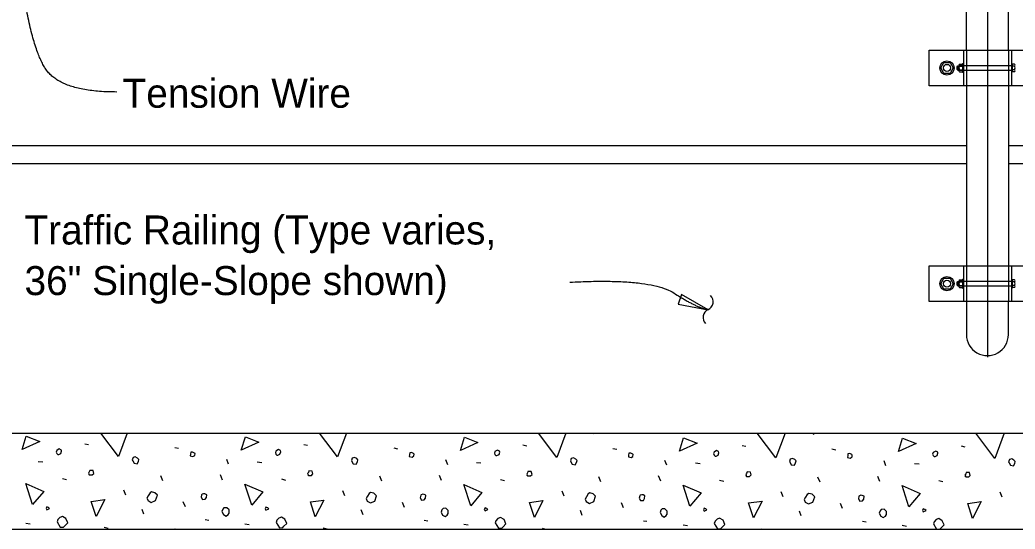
# Model space of a CAD drawing. Extents: x 0.5 to 39.7, y 0.9 to 25.6.
# Drawn here: x 5.48 to 12.4, y 13.47 to 17.01 of the extents above; entities that cross this region are included whole.
import ezdxf

# ---------------------------------------------------------------- set-up
doc = ezdxf.new("R2010")
doc.units = 0
for name, color, linetype in [('CL_Major', 7, 'Continuous'), ('Dimension', 7, 'Continuous'), ('Miscellaneous', 7, 'Continuous'), ('SteelMisc', 7, 'Continuous'), ('SteelMisc_h', 7, 'Continuous'), ('SupstrConc', 7, 'Continuous'), ('TextStructures', 7, 'Continuous')]:
    doc.layers.add(name, color=color, linetype=linetype)

msp = doc.modelspace()

# ---------------------------------------------------------------- linework, layer by layer
at = {"layer": 'CL_Major'}
msp.add_line((12.2062, 24.6326), (12.2062, 14.6639), dxfattribs=at)
at = {"layer": 'Dimension'}
msp.add_lwpolyline([(10.2634, 14.9952), (10.0798, 15.0997), (10.0556, 15.0334)], close=True, dxfattribs=at)
for centre, start, end in [((10.2392, 15.0503), 294.14658, 45.87379), ((10.2879, 14.9415), 114.14657, 225.87379)]:
    msp.add_arc(centre, 0.0596, start, end, dxfattribs=at)
for points in [[(6.1508, 16.5088), (5.753, 16.5088), (5.549, 16.8458), (5.4877, 17.3027)], [(9.3027, 15.1869), (9.8656, 15.2152), (10.187, 15.0071), (10.2636, 14.9959)]]:
    msp.add_open_spline(points, degree=2, dxfattribs=at)
at = {"layer": 'Miscellaneous'}
for p, q in [((11.9986, 16.6691), (11.9986, 16.6812)), ((12.0044, 16.6691), (12.0044, 16.6812)), ((11.9986, 15.1691), (11.9986, 15.1812)), ((12.0044, 15.1691), (12.0044, 15.1812)), ((7.9504, 14.1326), (7.9491, 14.1361)), ((9.4742, 14.129), (9.4716, 14.1361)), ((10.9981, 14.1255), (10.9942, 14.1361)), ((5.9281, 14.0619), (5.9546, 14.0566)), ((7.4519, 14.0583), (7.4784, 14.053)), ((8.9757, 14.0548), (9.0023, 14.0495)), ((10.4996, 14.0513), (10.5261, 14.046)), ((6.5539, 14.0371), (6.5804, 14.0318)), ((8.0777, 14.0336), (8.1042, 14.0283)), ((9.6015, 14.0301), (9.628, 14.0247)), ((11.1253, 14.0265), (11.1519, 14.0212)), ((12.0234, 14.0477), (12.0499, 14.0424)), ((5.6046, 13.9399), (5.6364, 13.9364)), ((6.9287, 13.9205), (6.9163, 13.954)), ((7.1284, 13.9364), (7.1602, 13.9328)), ((8.4525, 13.9169), (8.4401, 13.9505)), ((8.6522, 13.9328), (8.6841, 13.9293)), ((9.9763, 13.9134), (9.9639, 13.947)), ((10.1761, 13.9293), (10.2079, 13.9258)), ((11.5001, 13.9098), (11.4877, 13.9434)), ((11.6999, 13.9258), (11.7317, 13.9222)), ((6.8862, 13.8108), (6.8721, 13.8462)), ((5.7725, 13.8215), (5.8008, 13.8144)), ((6.4708, 13.8055), (6.4567, 13.8409)), ((7.2964, 13.8179), (7.3246, 13.8108)), ((7.9946, 13.802), (7.9805, 13.8374)), ((8.4101, 13.8073), (8.3959, 13.8427)), ((8.8202, 13.8144), (8.8485, 13.8073)), ((9.5184, 13.7985), (9.5043, 13.8338)), ((9.9339, 13.8038), (9.9197, 13.8391)), ((10.344, 13.8108), (10.3723, 13.8038)), ((11.0423, 13.7949), (11.0281, 13.8303)), ((11.4577, 13.8002), (11.4435, 13.8356)), ((11.8678, 13.8073), (11.8961, 13.8002)), ((6.2145, 13.7048), (6.2003, 13.7401)), ((7.7383, 13.7012), (7.7242, 13.7366)), ((9.2621, 13.6977), (9.248, 13.7331)), ((10.7859, 13.6942), (10.7718, 13.7295)), ((12.3097, 13.6906), (12.2956, 13.726)), ((6.6281, 13.6235), (6.614, 13.6588)), ((8.152, 13.6199), (8.1378, 13.6553)), ((9.6758, 13.6164), (9.6616, 13.6518)), ((11.1996, 13.6129), (11.1854, 13.6482)), ((6.34, 13.5722), (6.3276, 13.6058)), ((7.8638, 13.5687), (7.8514, 13.6023)), ((9.3876, 13.5651), (9.3753, 13.5987)), ((10.9114, 13.5616), (10.8991, 13.5952)), ((5.518, 13.5103), (5.548, 13.505)), ((6.766, 13.5351), (6.7908, 13.5315)), ((7.0418, 13.5068), (7.0719, 13.5015)), ((8.2898, 13.5315), (8.3146, 13.528)), ((8.5656, 13.5033), (8.5957, 13.498)), ((9.8137, 13.528), (9.8384, 13.5245)), ((10.0894, 13.4997), (10.1195, 13.4944)), ((11.3375, 13.5245), (11.3622, 13.5209)), ((6.0625, 13.482), (6.0907, 13.475)), ((7.5863, 13.4785), (7.6146, 13.4714)), ((9.1101, 13.475), (9.1322, 13.4695)), ((10.6339, 13.4714), (10.6418, 13.4695)), ((11.6132, 13.4962), (11.6433, 13.4909))]:
    msp.add_line(p, q, dxfattribs=at)
for points in [[(6.1632, 13.9753), (6.041, 14.1361)], [(6.2233, 14.1361), (6.1632, 13.9753)], [(7.687, 13.9717), (7.5621, 14.1361)], [(7.7485, 14.1361), (7.687, 13.9717)], [(9.2109, 13.9682), (9.0832, 14.1361)], [(9.2736, 14.1361), (9.2109, 13.9682)], [(10.7347, 13.9646), (10.6043, 14.1361)], [(10.7988, 14.1361), (10.7347, 13.9646)], [(12.2585, 13.9611), (12.1255, 14.1361)], [(12.3239, 14.1361), (12.2585, 13.9611)], [(5.4932, 14.023), (5.5215, 14.1149), (5.6152, 14.0778), (5.4932, 14.023)], [(7.0171, 14.0194), (7.0453, 14.1114), (7.139, 14.0742), (7.0171, 14.0194)], [(8.5409, 14.0159), (8.5692, 14.1078), (8.6628, 14.0707), (8.5409, 14.0159)], [(10.0647, 14.0124), (10.093, 14.1043), (10.1867, 14.0672), (10.0647, 14.0124)], [(11.5885, 14.0088), (11.6168, 14.1008), (11.7105, 14.0636), (11.5885, 14.0088)], [(5.7407, 13.9876), (5.7478, 13.9876), (5.7619, 13.9947), (5.7672, 14.0106), (5.7655, 14.0194), (5.7513, 14.0265), (5.7337, 14.0159), (5.7301, 14.0053), (5.7337, 13.9947), (5.7407, 13.9876)], [(6.6617, 13.9788), (6.6812, 13.9735), (6.6935, 13.9823), (6.6953, 13.9947), (6.6918, 13.9982), (6.6776, 14.0053), (6.6653, 14.0035), (6.6635, 13.9912), (6.6617, 13.9788)], [(7.2645, 13.9841), (7.2716, 13.9841), (7.2858, 13.9912), (7.2911, 14.0071), (7.2893, 14.0159), (7.2751, 14.023), (7.2575, 14.0124), (7.2539, 14.0018), (7.2575, 13.9912), (7.2645, 13.9841)], [(8.1855, 13.9753), (8.205, 13.9699), (8.2174, 13.9788), (8.2191, 13.9912), (8.2156, 13.9947), (8.2015, 14.0018), (8.1891, 14), (8.1873, 13.9876), (8.1855, 13.9753)], [(8.7884, 13.9806), (8.7954, 13.9806), (8.8096, 13.9876), (8.8149, 14.0035), (8.8131, 14.0124), (8.799, 14.0194), (8.7813, 14.0088), (8.7777, 13.9982), (8.7813, 13.9876), (8.7884, 13.9806)], [(9.7094, 13.9717), (9.7288, 13.9664), (9.7412, 13.9753), (9.7429, 13.9876), (9.7394, 13.9912), (9.7253, 13.9982), (9.7129, 13.9965), (9.7111, 13.9841), (9.7094, 13.9717)], [(10.3122, 13.977), (10.3192, 13.977), (10.3334, 13.9841), (10.3387, 14), (10.3369, 14.0088), (10.3228, 14.0159), (10.3051, 14.0053), (10.3016, 13.9947), (10.3051, 13.9841), (10.3122, 13.977)], [(11.2332, 13.9682), (11.2526, 13.9629), (11.265, 13.9717), (11.2668, 13.9841), (11.2632, 13.9876), (11.2491, 13.9947), (11.2367, 13.9929), (11.2349, 13.9806), (11.2332, 13.9682)], [(11.836, 13.9735), (11.8431, 13.9735), (11.8572, 13.9806), (11.8625, 13.9965), (11.8607, 14.0053), (11.8466, 14.0124), (11.8289, 14.0018), (11.8254, 13.9912), (11.8289, 13.9806), (11.836, 13.9735)], [(6.2622, 13.9434), (6.2711, 13.9275), (6.2923, 13.924), (6.3011, 13.9399), (6.3046, 13.954), (6.2958, 13.9629), (6.2799, 13.9717), (6.264, 13.9664), (6.2587, 13.9505), (6.2622, 13.9434)], [(7.786, 13.9399), (7.7949, 13.924), (7.8161, 13.9205), (7.8249, 13.9364), (7.8285, 13.9505), (7.8196, 13.9593), (7.8037, 13.9682), (7.7878, 13.9629), (7.7825, 13.947), (7.786, 13.9399)], [(9.3098, 13.9364), (9.3187, 13.9205), (9.3399, 13.9169), (9.3487, 13.9328), (9.3523, 13.947), (9.3434, 13.9558), (9.3275, 13.9646), (9.3116, 13.9593), (9.3063, 13.9434), (9.3098, 13.9364)], [(10.8337, 13.9328), (10.8425, 13.9169), (10.8637, 13.9134), (10.8726, 13.9293), (10.8761, 13.9434), (10.8672, 13.9523), (10.8513, 13.9611), (10.8354, 13.9558), (10.8301, 13.9399), (10.8337, 13.9328)], [(12.3575, 13.9293), (12.3663, 13.9134), (12.3875, 13.9098), (12.3964, 13.9258), (12.3999, 13.9399), (12.3911, 13.9487), (12.3752, 13.9576), (12.3592, 13.9523), (12.3539, 13.9364), (12.3575, 13.9293)], [(5.9599, 13.8462), (5.9811, 13.8462), (5.9917, 13.8568), (5.9864, 13.8763), (5.9635, 13.878), (5.9599, 13.8674), (5.9546, 13.8586), (5.9599, 13.8462), (5.9564, 13.8497)], [(7.4837, 13.8427), (7.505, 13.8427), (7.5156, 13.8533), (7.5103, 13.8727), (7.4873, 13.8745), (7.4837, 13.8639), (7.4784, 13.855), (7.4837, 13.8427), (7.4802, 13.8462)], [(9.0076, 13.8391), (9.0288, 13.8391), (9.0394, 13.8497), (9.0341, 13.8692), (9.0111, 13.871), (9.0076, 13.8603), (9.0023, 13.8515), (9.0076, 13.8391), (9.004, 13.8427)], [(10.5314, 13.8356), (10.5526, 13.8356), (10.5632, 13.8462), (10.5579, 13.8657), (10.5349, 13.8674), (10.5314, 13.8568), (10.5261, 13.848), (10.5314, 13.8356), (10.5278, 13.8391)], [(12.0552, 13.8321), (12.0764, 13.8321), (12.087, 13.8427), (12.0817, 13.8621), (12.0587, 13.8639), (12.0552, 13.8533), (12.0499, 13.8444), (12.0552, 13.8321), (12.0517, 13.8356)], [(5.5657, 13.6394), (5.518, 13.7861), (5.6435, 13.7313), (5.5657, 13.6394)], [(7.0895, 13.6358), (7.0418, 13.7826), (7.1673, 13.7278), (7.0895, 13.6358)], [(8.6133, 13.6323), (8.5656, 13.779), (8.6911, 13.7242), (8.6133, 13.6323)], [(10.1372, 13.6288), (10.0894, 13.7755), (10.2149, 13.7207), (10.1372, 13.6288)], [(6.3683, 13.6677), (6.3913, 13.6553), (6.4213, 13.6677), (6.4337, 13.7048), (6.416, 13.7225), (6.393, 13.7278), (6.3824, 13.7207), (6.37, 13.7012), (6.3612, 13.6853), (6.3683, 13.6677)], [(6.7377, 13.6906), (6.7466, 13.6747), (6.766, 13.6765), (6.7749, 13.6889), (6.7766, 13.7083), (6.7643, 13.7136), (6.7554, 13.7154), (6.7448, 13.7119), (6.7413, 13.7083), (6.7377, 13.6906)], [(7.8921, 13.6641), (7.9151, 13.6518), (7.9451, 13.6641), (7.9575, 13.7012), (7.9398, 13.7189), (7.9168, 13.7242), (7.9062, 13.7172), (7.8939, 13.6977), (7.885, 13.6818), (7.8921, 13.6641)], [(8.2616, 13.6871), (8.2704, 13.6712), (8.2898, 13.673), (8.2987, 13.6853), (8.3005, 13.7048), (8.2881, 13.7101), (8.2792, 13.7119), (8.2686, 13.7083), (8.2651, 13.7048), (8.2616, 13.6871)], [(9.4159, 13.6606), (9.4389, 13.6482), (9.4689, 13.6606), (9.4813, 13.6977), (9.4636, 13.7154), (9.4407, 13.7207), (9.4301, 13.7136), (9.4177, 13.6942), (9.4088, 13.6783), (9.4159, 13.6606)], [(9.7854, 13.6836), (9.7942, 13.6677), (9.8137, 13.6694), (9.8225, 13.6818), (9.8243, 13.7012), (9.8119, 13.7066), (9.8031, 13.7083), (9.7924, 13.7048), (9.7889, 13.7012), (9.7854, 13.6836)], [(10.9397, 13.6571), (10.9627, 13.6447), (10.9928, 13.6571), (11.0051, 13.6942), (10.9875, 13.7119), (10.9645, 13.7172), (10.9539, 13.7101), (10.9415, 13.6906), (10.9327, 13.6747), (10.9397, 13.6571)], [(11.3092, 13.68), (11.318, 13.6641), (11.3375, 13.6659), (11.3463, 13.6783), (11.3481, 13.6977), (11.3357, 13.703), (11.3269, 13.7048), (11.3163, 13.7012), (11.3127, 13.6977), (11.3092, 13.68)], [(11.661, 13.6252), (11.6132, 13.772), (11.7388, 13.7172), (11.661, 13.6252)], [(6.0077, 13.5581), (5.9741, 13.6624), (6.0678, 13.6747), (6.0077, 13.5581)], [(7.5315, 13.5545), (7.4979, 13.6588), (7.5916, 13.6712), (7.5315, 13.5545)], [(9.0553, 13.551), (9.0217, 13.6553), (9.1154, 13.6677), (9.0553, 13.551)], [(10.5791, 13.5475), (10.5455, 13.6518), (10.6392, 13.6641), (10.5791, 13.5475)], [(12.1029, 13.5439), (12.0693, 13.6482), (12.163, 13.6606), (12.1029, 13.5439)], [(5.6647, 13.604), (5.6842, 13.6129), (5.6771, 13.6199), (5.6647, 13.6252), (5.6594, 13.6129), (5.6647, 13.604)], [(6.8827, 13.5916), (6.8933, 13.5704), (6.911, 13.5598), (6.9251, 13.5704), (6.9322, 13.581), (6.9322, 13.6023), (6.9163, 13.6182), (6.8968, 13.6164), (6.888, 13.6076), (6.8827, 13.5916)], [(7.1885, 13.6005), (7.208, 13.6093), (7.2009, 13.6164), (7.1885, 13.6217), (7.1832, 13.6093), (7.1885, 13.6005)], [(8.4065, 13.5881), (8.4171, 13.5669), (8.4348, 13.5563), (8.4489, 13.5669), (8.456, 13.5775), (8.456, 13.5987), (8.4401, 13.6146), (8.4207, 13.6129), (8.4118, 13.604), (8.4065, 13.5881)], [(8.7123, 13.5969), (8.7318, 13.6058), (8.7247, 13.6129), (8.7123, 13.6182), (8.707, 13.6058), (8.7123, 13.5969)], [(9.9303, 13.5846), (9.9409, 13.5634), (9.9586, 13.5528), (9.9728, 13.5634), (9.9798, 13.574), (9.9798, 13.5952), (9.9639, 13.6111), (9.9445, 13.6093), (9.9356, 13.6005), (9.9303, 13.5846)], [(10.2362, 13.5934), (10.2556, 13.6023), (10.2485, 13.6093), (10.2362, 13.6146), (10.2309, 13.6023), (10.2362, 13.5934)], [(11.4541, 13.581), (11.4648, 13.5598), (11.4824, 13.5492), (11.4966, 13.5598), (11.5036, 13.5704), (11.5036, 13.5916), (11.4877, 13.6076), (11.4683, 13.6058), (11.4594, 13.5969), (11.4541, 13.581)], [(11.76, 13.5899), (11.7794, 13.5987), (11.7723, 13.6058), (11.76, 13.6111), (11.7547, 13.5987), (11.76, 13.5899)], [(5.7354, 13.5192), (5.7584, 13.482), (5.7814, 13.4838), (5.7902, 13.4927), (5.8097, 13.5121), (5.7973, 13.5421), (5.7725, 13.5563), (5.7549, 13.5492), (5.7407, 13.5351), (5.7354, 13.5192)], [(7.2592, 13.5156), (7.2822, 13.4785), (7.3052, 13.4803), (7.314, 13.4891), (7.3335, 13.5086), (7.3211, 13.5386), (7.2964, 13.5528), (7.2787, 13.5457), (7.2645, 13.5315), (7.2592, 13.5156)], [(8.7831, 13.5121), (8.806, 13.475), (8.829, 13.4767), (8.8379, 13.4856), (8.8573, 13.505), (8.8449, 13.5351), (8.8202, 13.5492), (8.8025, 13.5421), (8.7884, 13.528), (8.7831, 13.5121)], [(10.3069, 13.5086), (10.3298, 13.4714), (10.3528, 13.4732), (10.3617, 13.482), (10.3811, 13.5015), (10.3687, 13.5315), (10.344, 13.5457), (10.3263, 13.5386), (10.3122, 13.5245), (10.3069, 13.5086)], [(11.8738, 13.4695), (11.8766, 13.4697), (11.8855, 13.4785), (11.9049, 13.498), (11.8926, 13.528), (11.8678, 13.5421), (11.8501, 13.5351), (11.836, 13.5209), (11.8307, 13.505)], [(11.8307, 13.505), (11.8527, 13.4695)], [(6.5568, 13.4695), (6.5557, 13.4697), (6.5541, 13.4695)]]:
    msp.add_lwpolyline(points, dxfattribs=at)
at = {"layer": 'SteelMisc'}
for p, q in [((12.0604, 16.801), (12.0604, 17.2769)), ((12.3521, 16.801), (12.3521, 17.2769)), ((11.8002, 16.801), (12.6122, 16.801)), ((11.8002, 16.551), (11.8002, 16.801)), ((12.0396, 16.801), (12.0396, 16.551)), ((12.3729, 16.801), (12.3729, 16.551)), ((11.9958, 16.684), (12.0015, 16.6906)), ((11.9958, 16.6663), (11.9958, 16.684)), ((12.0015, 16.6906), (12.008, 16.6906)), ((12.0015, 16.6607), (12.0015, 16.6906)), ((12.008, 16.6939), (12.008, 16.6582)), ((12.0127, 16.689), (12.033, 16.689)), ((12.0129, 16.702), (12.033, 16.702)), ((12.033, 16.7063), (12.033, 16.6457)), ((12.033, 16.7063), (12.0396, 16.7063)), ((12.033, 16.702), (12.033, 16.65)), ((12.3792, 16.7063), (12.3731, 16.7063)), ((12.3939, 16.702), (12.3791, 16.702)), ((12.394, 16.689), (12.3791, 16.689)), ((12.3792, 16.7063), (12.3792, 16.6457)), ((11.9958, 16.6663), (12.0015, 16.6607)), ((12.0015, 16.6607), (12.008, 16.6607)), ((12.0127, 16.6631), (12.033, 16.6631)), ((12.013, 16.65), (12.033, 16.65)), ((12.033, 16.6457), (12.0396, 16.6457)), ((12.3792, 16.6457), (12.3731, 16.6457)), ((12.394, 16.663), (12.3791, 16.663)), ((12.3939, 16.65), (12.3791, 16.65)), ((12.6122, 16.551), (11.8002, 16.551)), ((12.0604, 16.551), (12.0604, 15.301)), ((12.3521, 16.551), (12.3521, 15.301)), ((11.8002, 15.301), (12.6122, 15.301)), ((11.8002, 15.051), (11.8002, 15.301)), ((12.0396, 15.301), (12.0396, 15.051)), ((12.3729, 15.301), (12.3729, 15.051)), ((11.9958, 15.184), (12.0015, 15.1906)), ((11.9958, 15.1663), (11.9958, 15.184)), ((11.9958, 15.1663), (12.0015, 15.1607)), ((12.0015, 15.1906), (12.008, 15.1906)), ((12.0015, 15.1607), (12.0015, 15.1906)), ((12.0015, 15.1607), (12.008, 15.1607)), ((12.008, 15.1939), (12.008, 15.1582)), ((12.0127, 15.189), (12.033, 15.189)), ((12.0127, 15.1631), (12.033, 15.1631)), ((12.0129, 15.202), (12.033, 15.202)), ((12.033, 15.2063), (12.033, 15.1457)), ((12.033, 15.2063), (12.0396, 15.2063)), ((12.033, 15.202), (12.033, 15.15)), ((12.3792, 15.2063), (12.3731, 15.2063)), ((12.3939, 15.202), (12.3791, 15.202)), ((12.394, 15.189), (12.3791, 15.189)), ((12.394, 15.163), (12.3791, 15.163)), ((12.3792, 15.2063), (12.3792, 15.1457)), ((12.013, 15.15), (12.033, 15.15)), ((12.033, 15.1457), (12.0396, 15.1457)), ((12.3792, 15.1457), (12.3731, 15.1457)), ((12.3939, 15.15), (12.3791, 15.15)), ((12.6122, 15.051), (11.8002, 15.051)), ((12.0603, 15.051), (12.0603, 14.8218)), ((12.3519, 14.8218), (12.3519, 15.051))]:
    msp.add_line(p, q, dxfattribs=at)
for points in [[(11.9036, 16.7135), (11.9469, 16.7135), (11.9686, 16.676), (11.9469, 16.6385), (11.9036, 16.6385), (11.8819, 16.676)], [(11.9036, 15.2135), (11.9469, 15.2135), (11.9686, 15.176), (11.9469, 15.1385), (11.9036, 15.1385), (11.8819, 15.176)]]:
    msp.add_lwpolyline(points, close=True, dxfattribs=at)
for centre, radius in [((11.9252, 16.676), 0.05), ((11.9252, 16.676), 0.025), ((11.9252, 15.176), 0.05), ((11.9252, 15.176), 0.025)]:
    msp.add_circle(centre, radius, dxfattribs=at)
for centre, radius, start, end in [((12.0145, 16.6955), 0.00674, 104.48908, 254.18889), ((12.0274, 16.676), 0.0196, 138.62797, 221.37203), ((12.3922, 16.6955), 0.00673, 285.7823, 75.54039), ((12.3793, 16.676), 0.0196, 318.62797, 41.37203), ((12.0145, 16.6565), 0.00673, 105.7823, 255.54039), ((12.3922, 16.6565), 0.00674, 284.48908, 74.18889), ((12.0145, 15.1955), 0.00674, 104.48908, 254.18889), ((12.0274, 15.176), 0.0196, 138.62797, 221.37203), ((12.0145, 15.1565), 0.00673, 105.7823, 255.54039), ((12.3922, 15.1955), 0.00673, 285.7823, 75.54039), ((12.3922, 15.1565), 0.00674, 284.48908, 74.18889), ((12.3793, 15.176), 0.0196, 318.62797, 41.37203)]:
    msp.add_arc(centre, radius, start, end, dxfattribs=at)
msp.add_ellipse((12.2062, 14.8218), major_axis=(0, 0.1458), ratio=0.999499, start_param=1.570796, end_param=4.712389, dxfattribs=at)
at = {"layer": 'SteelMisc_h'}
for p, q in [((12.0604, 16.801), (12.0604, 16.551)), ((12.3521, 16.801), (12.3521, 16.551)), ((12.3729, 16.6906), (12.008, 16.6906)), ((12.008, 16.6607), (12.3729, 16.6607)), ((12.0604, 15.301), (12.0604, 15.051)), ((12.3521, 15.301), (12.3521, 15.051)), ((12.3729, 15.1906), (12.008, 15.1906)), ((12.008, 15.1607), (12.3729, 15.1607))]:
    msp.add_line(p, q, dxfattribs=at)
at = {"layer": 'SupstrConc'}
for p, q in [((2.352, 16.1361), (12.0604, 16.1361)), ((12.3521, 16.1361), (22.0604, 16.1361)), ((2.352, 16.0111), (12.0604, 16.0111)), ((12.3521, 16.0111), (22.0604, 16.0111)), ((0.8193, 14.1361), (23.5931, 14.1361)), ((0.8193, 13.4695), (23.5931, 13.4695))]:
    msp.add_line(p, q, dxfattribs=at)

# ---------------------------------------------------------------- texts
at = {"layer": 'Dimension'}
for s, p in [('Traffic Railing (Type varies,', (5.5094, 15.4486)), ('36" Single-Slope shown)', (5.5094, 15.0966))]:
    msp.add_text(s, height=0.2016, dxfattribs=at).set_placement(p)
at = {"layer": 'TextStructures'}
msp.add_text('Tension Wire', height=0.2016, dxfattribs=at).set_placement((6.1918, 16.3995))

doc.saveas('drawing.dxf')
